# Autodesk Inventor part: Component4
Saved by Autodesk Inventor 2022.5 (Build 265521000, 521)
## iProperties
Created: 2024-12
Part Number: Component4
Material: Generic
Document SubType Name: Modeling
Designer: AdminForWorker
Density: 1 g/cm^3
Appearance: Default
Title: Component4
Author: AdminForWorker
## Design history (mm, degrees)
feature "Body2"
body "Solid1"
